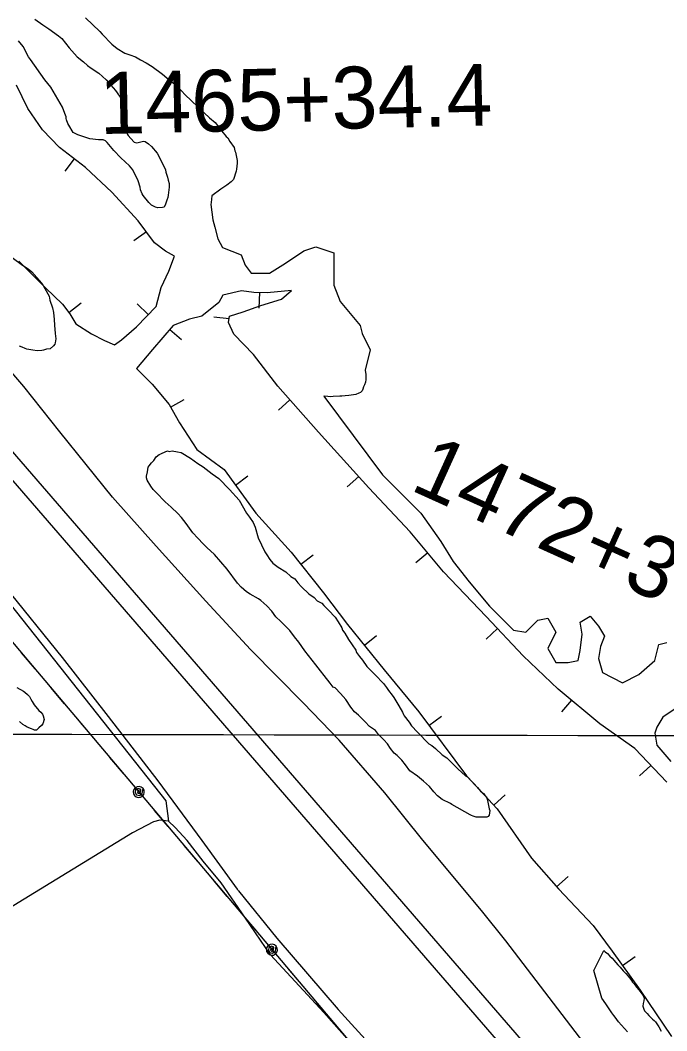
# Model space of a CAD drawing. Extents: x 3187622 to 3225504, y 800805 to 826213.
# Drawn here: x 3200890 to 3201935, y 811808 to 813444 of the extents above; entities that cross this region are included whole.
import ezdxf

# ---------------------------------------------------------------- set-up
doc = ezdxf.new("R2010")
doc.units = 0
for name, color, linetype in [('V-BORW-LINE', 7, 'Continuous'), ('V-GRID-MAJR', 7, 'Continuous'), ('V-LEVE-TOET', 7, 'Continuous'), ('V-SITE-VEGE', 7, 'Continuous'), ('V-SURV-IDEN', 7, 'Continuous'), ('V-SURV-LINE', 7, 'Continuous'), ('V-TOPO-SHOR', 7, 'Continuous'), ('V-UTIL-LINE', 7, 'Continuous')]:
    doc.layers.add(name, color=color, linetype=linetype)

msp = doc.modelspace()

# ---------------------------------------------------------------- linework, layer by layer
at = {"layer": 'V-BORW-LINE'}
for p, q in [((3200977.058, 813219.439), (3200961.941, 813199.527)), ((3201093.68, 813101.234), (3201073.463, 813086.527)), ((3201276.596, 813002.88), (3201275.815, 812977.892)), ((3200968.341, 812970.857), (3200988.063, 812986.22)), ((3201096.736, 812967.344), (3201078.607, 812984.558)), ((3201227.455, 812960.406), (3201202.619, 812963.261)), ((3201131.421, 812943.331), (3201150.3850000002, 812927.041)), ((3201132.784, 812817.746), (3201154.594, 812829.9670000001)), ((3201326.003, 812829.295), (3201307.2970000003, 812812.709)), ((3201237.724, 812691.53), (3201257.961, 812706.208)), ((3201437.168, 812705.208), (3201418.61, 812688.457)), ((3201343.613, 812563.187), (3201363.242, 812578.669)), ((3201548.7630000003, 812581.595), (3201529.47, 812565.6950000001)), ((3201446.355, 812432.05), (3201465.8310000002, 812447.725)), ((3201661.782, 812459.309), (3201643.565, 812442.187)), ((3201781.194, 812343.348), (3201765.202, 812324.133)), ((3201550.852, 812302.333), (3201570.9220000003, 812317.24)), ((3201909.501, 812237.79), (3201891.386, 812220.561)), ((3201655.677, 812173.1510000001), (3201673.995, 812190.164)), ((3201757.113, 812041.3030000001), (3201775.968, 812057.719)), ((3201863.927, 811913.929), (3201884.307, 811928.409))]:
    msp.add_line(p, q, dxfattribs=at)
for points in [[(3200887.498, 813053.732), (3200930.353, 813010.537), (3200958.1350000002, 812983.958), (3200970.005, 812968.72), (3200979.662, 812952.273), (3201004.745, 812936.052), (3201025.842, 812925.43), (3201042.232, 812918.322), (3201053.3510000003, 812926.591), (3201077.921, 812947.528), (3201109.417, 812980.699), (3201117.8680000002, 813011.344), (3201129.921, 813037.87), (3201139.399, 813062.145), (3201124.7090000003, 813070.012), (3201106.701, 813083.335), (3201080.608, 813119.203), (3201037.947, 813165.2930000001), (3200995.194, 813205.67), (3200953.042, 813237.671), (3200925.686, 813266.257), (3200901.8310000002, 813300.812), (3200883.433, 813338.685)], [(3201935.4790000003, 812210.476), (3201883.686, 812264.933), (3201827.063, 812305.1730000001), (3201759.676, 812361.257), (3201703.29, 812415.148), (3201643.394, 812478.872), (3201574.071, 812550.884), (3201520.467, 812615.93), (3201453.6010000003, 812687.002), (3201372.305, 812777.071), (3201306.521, 812851.269), (3201266.847, 812902.878), (3201235.2970000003, 812935.4280000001), (3201226.8000000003, 812954.7050000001), (3201227.961, 812964.805), (3201250.223, 812971.552), (3201278.828, 812981.8470000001), (3201312.478, 812992.192), (3201328.36, 813006.442), (3201288.936, 813002.4940000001), (3201267.269, 813003.171), (3201247.585, 813005.944), (3201217.4620000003, 812999.046), (3201211.127, 812986.9670000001), (3201183.38, 812964.885), (3201163.474, 812960.0160000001), (3201136.798, 812949.591), (3201103.576, 812910.914), (3201077.826, 812880.062)], [(3201077.826, 812880.062), (3201103.311, 812854.907), (3201130.64, 812821.573), (3201147.1750000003, 812792.0650000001), (3201175.414, 812749.171), (3201219.65, 812716.448), (3201270.935, 812645.742), (3201328.078, 812582.882), (3201379.982, 812517.077), (3201419.2830000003, 812465.688), (3201478.159, 812392.534), (3201534.463, 812324.399), (3201611.366, 812220.861), (3201660.998, 812167.422), (3201716.899, 812087.4890000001), (3201760.1890000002, 812037.77), (3201816.626, 811978.835), (3201847.374, 811937.2270000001), (3201892.2800000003, 811874.024), (3201942.869, 811798.711)]]:
    msp.add_lwpolyline(points, dxfattribs=at)
at = {"layer": 'V-GRID-MAJR'}
msp.add_spline([(3191808.85, 812309.639), (3197045.574, 812297.071), (3202282.3000000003, 812285.265), (3207519.028, 812274.221), (3212755.758, 812263.939), (3217992.489, 812254.4180000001), (3223229.221, 812245.659), (3223229.222, 812245.659)], degree=3, dxfattribs=at)
at = {"layer": 'V-LEVE-TOET'}
for q in [(3201242.369, 812035.256), (3201304.645, 811957.9990000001)]:
    msp.add_line((3201242.969, 812034.51), q, dxfattribs=at)
for points in [[(3201635.636, 812003.04), (3201540.65, 812116.85), (3201479.235, 812193.443), (3201405.7970000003, 812278.7220000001), (3201347.636, 812338.677), (3201262.198, 812425.162), (3201189.762, 812503.432), (3201109.741, 812592.738), (3201039.115, 812672.112), (3200953.722, 812777.772), (3200895.489, 812850.892), (3200816.965, 812941.956), (3200731.278, 813040.961), (3200653.946, 813134.763), (3200589.761, 813211.086), (3200503.467, 813312.214), (3200414.8170000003, 813417.615), (3200326.1720000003, 813523.175)], [(3201242.369, 812035.256), (3201240.856, 812037.136), (3201183.708, 812115.922), (3201112.774, 812212.854), (3201032.379, 812316.63), (3200958.17, 812412.323), (3200865, 812527.724), (3200772.132, 812641.818), (3200667.657, 812752.561), (3200559.123, 812863.383), (3200469.325, 812968.152), (3200416.6520000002, 813043.115), (3200375.737, 813104.037), (3200264.162, 813234.095), (3200148.125, 813368.7880000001), (3200039.261, 813496.192)], [(3201850.146, 811724.693), (3201675.275, 811953.503), (3201635.636, 812003.04)], [(3201304.645, 811957.9990000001), (3201404.0810000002, 811842.635), (3201507.392, 811728.623)]]:
    msp.add_lwpolyline(points, dxfattribs=at)
at = {"layer": 'V-SITE-VEGE'}
for points in [[(3200913.491, 813445.715), (3200926.176, 813436.28), (3200935.859, 813429.964), (3200951.571, 813418.632), (3200957.003, 813414.237), (3200968.969, 813399.299), (3200981.548, 813384.351), (3200991.808, 813376.186), (3200998.44, 813370.5430000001), (3201004.481, 813366.136), (3201016.577, 813357.938), (3201028.629, 813347.286), (3201043.611, 813329.841), (3201050.185, 813321.135), (3201059.6890000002, 813305.632), (3201061.432, 813300.696), (3201061.948, 813295.783), (3201061.713, 813283.532), (3201062.2430000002, 813279.233), (3201062.137, 813273.72), (3201060.875, 813271.908), (3201060.169, 813267.019), (3201063.077, 813258.997), (3201064.267, 813257.135), (3201068.461, 813252.1510000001), (3201073.866, 813246.533), (3201078.13, 813245.2220000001), (3201089.215, 813248.0750000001), (3201091.6550000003, 813247.4130000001), (3201097.096, 813243.633), (3201101.913, 813239.25), (3201110.9, 813228.66), (3201119.18, 813213.179), (3201124.468, 813201.436), (3201125.0100000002, 813197.747), (3201127.919, 813189.725), (3201129.049, 813184.802), (3201130.7800000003, 813179.2540000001), (3201130.671, 813173.741), (3201129.201, 813160.902), (3201128.504, 813156.626)], [(3200995.046, 813447.62), (3201018.525, 813425.721), (3201022.117, 813421.36), (3201037.735, 813405.128)], [(3201052.544, 813221.207), (3201041.128, 813233.071), (3201030.352, 813246.15), (3201027.3370000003, 813248.657), (3201023.686, 813249.953), (3201016.335, 813250.094), (3201002.27, 813251.591), (3200982.787, 813258.096), (3200975.506, 813261.9130000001), (3200968.381, 813273.693), (3200966.6040000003, 813276.79), (3200964.259, 813282.3520000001), (3200963.694, 813284.812), (3200963.741, 813287.263), (3200962.0100000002, 813292.812), (3200957.924, 813303.308), (3200938.937, 813335.539), (3200929.363, 813347.366), (3200906.1, 813380.294), (3200903.12, 813384.64), (3200894.252, 813401.356), (3200887.078, 813410.686)], [(3201037.735, 813405.128), (3201046.181, 813398.224), (3201058.903, 813390.6240000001), (3201066.819, 813388.0210000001), (3201075.946, 813384.781), (3201084.427, 813379.716), (3201093.52, 813374.637), (3201103.216, 813368.936), (3201119.518, 813356.363), (3201130.378, 813347.5750000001), (3201137.622, 813341.92), (3201140.012, 813338.812), (3201150.85, 813328.797), (3201155.6550000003, 813323.8), (3201166.478, 813313.177), (3201186.94, 813293.784), (3201195.974, 813285.6460000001), (3201205.02, 813278.117), (3201215.786, 813264.426), (3201222.97, 813255.71), (3201225.373, 813253.213), (3201228.9420000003, 813247.6290000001), (3201235.49, 813237.698), (3201236.61, 813232.16), (3201237.798, 813230.3), (3201240.602, 813216.765), (3201240.518, 813212.4770000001), (3201239.717, 813202.687), (3201239.045, 813199.638), (3201234.4960000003, 813186.2440000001), (3201230.738, 813182.027), (3201223.894, 813176.645), (3201220.795, 813174.865), (3201213.963, 813170.095), (3201199.662, 813159.339), (3201198.237, 813148.954), (3201198.165, 813145.278), (3201201.366, 813120.706), (3201204.205, 813109.008), (3201209.3510000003, 813089.912), (3201217.041, 813075.67), (3201246.9930000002, 813063.909), (3201253.52, 813047.5800000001), (3201263.316, 813034.5160000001), (3201292.6920000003, 813034.5160000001), (3201318.809, 813050.844), (3201348.187, 813070.4400000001), (3201367.772, 813076.973), (3201397.153, 813067.1730000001), (3201397.153, 813014.9180000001), (3201406.944, 812988.794), (3201423.267, 812969.201), (3201439.5870000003, 812949.606), (3201442.8540000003, 812936.541), (3201455.91, 812910.415), (3201447.656, 812877.184), (3201448.488, 812870.2660000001), (3201448.73, 812866.037), (3201448.498, 812862.465), (3201447.921, 812857.763), (3201446.546, 812853.89), (3201445.176, 812850.341), (3201443.964, 812846.464), (3201442.61, 812843.726), (3201440.29, 812841.332), (3201437.5, 812839.925), (3201432.4250000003, 812838.074), (3201428.512, 812837.336), (3201421.0160000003, 812836.343), (3201414.997, 812835.9720000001), (3201410.112, 812835.577), (3201406.5330000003, 812835.323), (3201395.955, 812834.551), (3201390.91, 812834.324), (3201387.181, 812834.721), (3201381.502, 812835.155), (3201380.8140000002, 812835.309), (3201475.497, 812707.935), (3201537.519, 812645.883), (3201570.162, 812600.164), (3201589.747, 812567.5040000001), (3201615.863, 812534.8470000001), (3201648.508, 812495.656), (3201687.678, 812456.468), (3201707.2630000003, 812453.201), (3201726.85, 812472.796), (3201743.171, 812476.063), (3201756.2290000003, 812453.201), (3201743.171, 812427.0750000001), (3201756.2290000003, 812404.213), (3201775.8140000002, 812404.213), (3201792.136, 812407.48), (3201795.401, 812423.808), (3201798.665, 812449.935), (3201795.401, 812469.53), (3201811.721, 812479.327), (3201824.779, 812462.9990000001), (3201834.573, 812446.6680000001), (3201828.044, 812430.339), (3201824.779, 812410.7440000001), (3201831.308, 812387.884)], [(3201128.504, 813156.626), (3201126.583, 813152.3740000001), (3201124.627, 813146.283), (3201122.696, 813141.417), (3201119.622, 813140.8640000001), (3201112.2600000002, 813140.393), (3201108.596, 813141.077), (3201101.917, 813144.27), (3201097.713, 813148.64), (3201088.736, 813159.843), (3201086.9590000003, 813162.942), (3201084.014, 813169.127), (3201083.483, 813173.427), (3201080.622, 813183.899), (3201071.779, 813201.839), (3201066.382, 813208.071), (3201052.544, 813221.207)], [(3200876.623, 813059.772), (3200893.537, 813047.189), (3200902.62, 813041.497), (3200908.651, 813036.482), (3200924.845, 813018.3960000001), (3200936.6950000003, 812997.332), (3200937.79, 812990.572), (3200941.841, 812978.237), (3200943.535, 812970.8520000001), (3200944.537, 812959.188), (3200944.973, 812949.9890000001), (3200945.937, 812936.49), (3200946.9960000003, 812927.8910000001), (3200946.265, 812921.777), (3200945.608, 812919.338), (3200943.719, 812916.924), (3200938.114, 812912.1290000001), (3200931.9760000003, 812911.636), (3200927.04, 812909.893), (3200924.579, 812909.328), (3200917.214, 812908.857), (3200909.876, 812909.61), (3200900.111, 812911.638), (3200897.6720000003, 812912.297), (3200892.8200000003, 812914.843), (3200888.557, 812916.152)], [(3201587.951, 812174.554), (3201585.509, 812175.834), (3201572.072, 812182.259), (3201564.798, 812188.561), (3201558.754, 812194.844), (3201551.5270000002, 812203.613), (3201541.8340000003, 812212.43), (3201532.1180000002, 812220.0160000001), (3201519.9590000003, 812228.878), (3201512.756, 812238.88), (3201506.737, 812246.394), (3201499.485, 812253.933), (3201494.627, 812257.724), (3201488.61, 812265.238), (3201483.8200000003, 812272.7270000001), (3201477.778, 812279.008), (3201469.318, 812287.801), (3201464.507, 812294.059), (3201454.767, 812300.41), (3201447.517, 812307.949), (3201436.6380000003, 812319.2540000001), (3201430.572, 812324.302), (3201424.555, 812331.816), (3201416.164, 812344.307), (3201407.7290000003, 812354.332), (3201399.268, 812363.126), (3201395.594, 812364.429), (3201390.7830000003, 812370.685), (3201381.166, 812383.203), (3201375.145, 812390.7170000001), (3201367.94, 812400.715), (3201349.8850000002, 812423.255), (3201340.286, 812437.0040000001), (3201333.059, 812445.7710000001), (3201325.8540000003, 812455.773), (3201321.018, 812460.799), (3201311.352, 812470.849), (3201302.867, 812478.41), (3201296.87, 812487.157), (3201288.41, 812495.947), (3201278.719, 812504.7660000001), (3201275.069, 812507.301), (3201261.6550000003, 812514.959), (3201255.5640000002, 812518.774), (3201247.0810000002, 812526.335), (3201241.04, 812532.616), (3201224.213, 812555.132), (3201203.715, 812578.952), (3201191.605, 812590.282), (3201185.5640000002, 812596.563), (3201177.1010000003, 812605.355), (3201168.6410000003, 812614.149), (3201157.836, 812629.153), (3201150.633, 812639.153), (3201144.589, 812645.435), (3201133.69, 812655.509), (3201123.997, 812664.3250000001), (3201109.4930000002, 812679.4010000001), (3201104.659, 812684.424), (3201101.057, 812689.426), (3201095.085, 812699.404), (3201093.924, 812703.125), (3201093.973, 812705.593), (3201095.347, 812712.959), (3201096.721, 812720.332), (3201098.001, 812722.7710000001), (3201101.794, 812727.627), (3201105.565, 812731.256), (3201109.378, 812737.3470000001), (3201114.379, 812740.947), (3201116.87, 812742.133), (3201119.358, 812743.319), (3201128.056, 812746.8470000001), (3201130.497, 812745.567), (3201135.449, 812746.704), (3201144.053, 812745.305), (3201150.191, 812743.956), (3201164.813, 812735.0430000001), (3201176.97, 812726.177), (3201185.502, 812721.082), (3201200.076, 812709.7050000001), (3201211.024, 812702.0970000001), (3201227.9450000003, 812684.506), (3201243.631, 812666.947), (3201255.552, 812645.758), (3201260.361, 812639.502), (3201266.357, 812630.755), (3201269.913, 812623.29), (3201274.508, 812605.941), (3201285.174, 812583.542), (3201288.775, 812578.5430000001), (3201293.561, 812571.0530000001), (3201298.372, 812564.797), (3201306.879, 812558.466), (3201319.06, 812550.835), (3201327.543, 812543.274), (3201333.634, 812539.459), (3201338.4450000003, 812533.2000000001), (3201344.488, 812526.919), (3201356.596, 812515.589), (3201365.106, 812509.261)], [(3201365.106, 812509.261), (3201369.9390000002, 812504.237), (3201377.2630000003, 812500.397), (3201380.8880000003, 812496.6290000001), (3201388.139, 812489.09), (3201399.0160000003, 812477.785), (3201403.805, 812470.296), (3201409.775, 812460.318), (3201410.936, 812456.5970000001), (3201414.538, 812451.596), (3201420.5100000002, 812441.618), (3201432.499, 812424.126), (3201433.66, 812420.404), (3201438.471, 812414.148), (3201443.2800000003, 812407.893), (3201450.487, 812397.889), (3201455.3200000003, 812392.865), (3201463.7800000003, 812384.071), (3201477.076, 812370.253), (3201481.887, 812363.9940000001), (3201485.487, 812358.993), (3201491.506, 812351.481), (3201493.9, 812347.735), (3201502.264, 812334.014), (3201508.236, 812324.0380000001), (3201509.397, 812320.3150000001), (3201510.5810000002, 812317.826), (3201519.019, 812307.799), (3201522.597, 812301.567), (3201532.267, 812291.518), (3201550.394, 812272.674), (3201555.2770000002, 812270.1140000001), (3201561.343, 812265.066), (3201572.244, 812254.992), (3201579.544, 812249.921), (3201597.697, 812232.31), (3201609.805, 812220.98), (3201613.454, 812218.443), (3201620.7060000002, 812210.906), (3201623.125, 812208.393), (3201629.167, 812202.112), (3201633.977, 812195.856), (3201638.835, 812192.0650000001), (3201641.252, 812189.552), (3201643.67, 812187.039), (3201644.832, 812183.318), (3201645.968, 812178.366), (3201648.217, 812167.2270000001), (3201649.403, 812164.736), (3201648.031, 812157.365), (3201646.749, 812154.922), (3201644.258, 812153.741), (3201641.795, 812153.7880000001), (3201634.399, 812153.931), (3201627.004, 812154.074), (3201622.1010000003, 812155.399), (3201619.66, 812156.681), (3201617.219, 812157.961), (3201587.951, 812174.554)], [(3201831.308, 812387.884), (3201863.951, 812371.556), (3201890.065, 812384.62), (3201916.179, 812407.48), (3201922.708, 812433.606), (3201935.7660000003, 812436.872)], [(3200884.233, 812363.6240000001), (3200894.733, 812357.92), (3200897.06, 812356.304), (3200901.309, 812352.685), (3200904.383, 812349.091), (3200907.056, 812345.11), (3200908.944, 812341.145), (3200912.373, 812335.578), (3200919.668, 812326.792), (3200922.756, 812323.983), (3200925.4390000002, 812320.394), (3200926.965, 812318.009), (3200928.421, 812312.088), (3200926.322, 812305.055), (3200924.304, 812302.343), (3200919.514, 812298.508), (3200915.9050000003, 812294.647), (3200912.762, 812294.708), (3200910.8200000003, 812295.925), (3200907.693, 812296.7710000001), (3200900.679, 812299.656), (3200897.574, 812301.682), (3200894.078, 812303.714), (3200888.278, 812308.541)], [(3201978.201, 812348.696), (3201929.235, 812316.036), (3201919.446, 812299.708), (3201916.179, 812289.91), (3201919.446, 812270.3150000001), (3201942.296, 812244.188)], [(3201872.006, 811806.512), (3201857.592, 811822.419), (3201852.196, 811830.138), (3201849.943, 811832.8640000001), (3201846.795, 811837.404), (3201836.901, 811851.935), (3201830.606, 811861.0160000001), (3201817.3680000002, 811905.9670000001), (3201833.79, 811938.123), (3201835.793, 811936.104), (3201839.488, 811933.0750000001), (3201843.41, 811929.118), (3201846.8710000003, 811925.858), (3201849.869, 811922.599), (3201853.328, 811918.644), (3201856.325, 811915.155), (3201860.0130000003, 811910.9670000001), (3201864.857, 811905.384), (3201869.471, 811900.729), (3201873.159, 811896.54)], [(3201873.159, 811896.54), (3201875, 811893.982), (3201878.457, 811889.333), (3201880.298, 811886.7760000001), (3201882.605, 811883.984), (3201886.752, 811878.635), (3201890.211, 811874.68), (3201892.054, 811872.1240000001), (3201894.127, 811869.566), (3201897.811, 811864.219), (3201898.722, 811860.7390000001), (3201898.472, 811856.801), (3201897.063, 811852.404), (3201896.58, 811848.003), (3201898.18, 811843.1290000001), (3201899.558, 811840.341), (3201903.943, 811836.1510000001), (3201906.7090000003, 811833.126), (3201909.247, 811830.335), (3201912.245, 811827.078), (3201915.0160000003, 811824.979), (3201917.324, 811822.6510000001), (3201919.395, 811819.63), (3201922.85, 811814.5160000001), (3201926.526, 811807.3150000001)]]:
    msp.add_lwpolyline(points, dxfattribs=at)
at = {"layer": 'V-SURV-LINE'}
for points in [[(3200848.4885279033, 812777.7262691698), (3202042.223007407, 811397.6839535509)], [(3202019.5401787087, 811378.0500700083), (3200825.805500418, 812758.092615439)]]:
    msp.add_lwpolyline(points, dxfattribs=at)
at = {"layer": 'V-TOPO-SHOR'}
for points in [[(3200263.097179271, 812777.344322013), (3200422.687365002, 812877.7316969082), (3200456.149823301, 812895.7499436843), (3200479.316140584, 812913.7681904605), (3200765.034053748, 812592.0137837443), (3200801.0705473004, 812589.4397484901), (3201125.3989892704, 812180.1681431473), (3201129.428, 812147.361)], [(3201422.106, 811790.63), (3201380.998, 811837.964), (3201294.2430000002, 811931.363), (3201254.268, 811990.421), (3201214.707, 812047.664), (3201185.56, 812082.566), (3201159.5500000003, 812116.0530000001), (3201140.528, 812137.2050000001), (3201129.428, 812147.361), (3201115.452, 812148.985), (3201105.464, 812146.466), (3201071.232, 812128.603), (3200720.076, 811913.985), (3200558.075, 811807.77)]]:
    msp.add_lwpolyline(points, dxfattribs=at)
at = {"layer": 'V-UTIL-LINE'}
for points in [[(3199923.052, 813594.495), (3200640.007, 812717.791), (3202006.057, 811098.7220000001), (3203128.651, 810686.063), (3203334.131, 810414.071), (3203687.083, 810134.035), (3205008.028, 808523.125), (3206196.963, 808326.532), (3208534.471, 807926.9400000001), (3209217.676, 808075.196), (3210991.348, 807487.653), (3211714.811, 807276.317), (3211555.069, 806654.4670000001), (3211454.5700000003, 806207.443)], [(3200891.1550000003, 812420.125), (3200913.08, 812394.139)], [(3200938.874, 812363.567), (3200960.799, 812337.581)], [(3200986.593, 812307.01), (3201008.518, 812281.024)], [(3201034.312, 812250.452), (3201056.237, 812224.466)], [(3201081.3880000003, 812194.657), (3201082.1410000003, 812197.434), (3201079.952, 812196.645), (3201079.301, 812193.9770000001), (3201081.4250000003, 812191.962), (3201084.123, 812194.027), (3201084.633, 812198.688), (3201080.773, 812200.506), (3201076.355, 812198.4720000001), (3201075.741, 812193.935), (3201077.8140000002, 812189.974), (3201082.56, 812189.112), (3201086.969, 812192.41), (3201088.267, 812200.461), (3201085.523, 812202.652), (3201082.148, 812203.625), (3201078.6580000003, 812203.233), (3201075.585, 812201.536), (3201073.394, 812198.792), (3201072.42, 812195.417), (3201072.812, 812191.9280000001), (3201074.5100000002, 812188.854), (3201077.254, 812186.6630000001), (3201080.628, 812185.689), (3201084.1180000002, 812186.081), (3201087.1920000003, 812187.779), (3201089.383, 812190.523), (3201090.356, 812193.897), (3201089.964, 812197.387), (3201088.267, 812200.461)], [(3201106.536, 812164.851), (3201128.461, 812138.865)], [(3201154.255, 812108.2930000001), (3201176.18, 812082.307)], [(3201201.974, 812051.736), (3201223.899, 812025.75)], [(3201249.693, 811995.1780000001), (3201271.6180000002, 811969.192)], [(3201296.771, 811939.382), (3201297.524, 811942.159), (3201295.335, 811941.3690000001), (3201294.684, 811938.701), (3201296.808, 811936.686), (3201299.506, 811938.752), (3201300.0160000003, 811943.412), (3201296.1550000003, 811945.23), (3201291.738, 811943.196), (3201291.124, 811938.659), (3201293.197, 811934.698), (3201297.943, 811933.837), (3201302.352, 811937.134), (3201303.65, 811945.185), (3201300.9050000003, 811947.376), (3201297.531, 811948.35), (3201294.041, 811947.958), (3201290.967, 811946.26), (3201288.7770000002, 811943.5160000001), (3201287.803, 811940.142), (3201288.1950000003, 811936.652), (3201289.892, 811933.578), (3201292.637, 811931.387), (3201296.011, 811930.414), (3201299.501, 811930.806), (3201302.575, 811932.503), (3201304.765, 811935.247), (3201305.739, 811938.622), (3201305.347, 811942.111), (3201303.65, 811945.185)], [(3201321.917, 811909.577), (3201343.842, 811883.591)], [(3201369.636, 811853.019), (3201391.561, 811827.033)]]:
    msp.add_lwpolyline(points, dxfattribs=at)

# ---------------------------------------------------------------- texts
at = {"layer": 'V-SURV-IDEN'}
for s, height, rotation, p in [('1465+34.4', 100, 1.2694876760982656, (3201018.5800904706, 813259.4619358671)), ('1472+37.2', 100.00000000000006, 335.6537454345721, (3201518.148557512, 812684.5402523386))]:
    msp.add_text(s, height=height, rotation=rotation, dxfattribs=at).set_placement(p)

doc.saveas('drawing.dxf')
